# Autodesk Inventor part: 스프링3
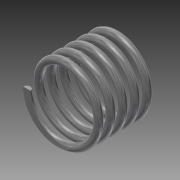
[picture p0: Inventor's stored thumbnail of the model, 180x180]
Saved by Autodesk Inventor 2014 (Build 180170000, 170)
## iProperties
Created: 2016-10
Part Number: 스프링3
Material: 강철, 탄소
Document SubType Name: Modeling
Designer: 703-16
Density: 7.87 g/cm^3
Appearance: 반연마
Mass: 6.81239 g
Surface Area: 17.6676 cm^2
Volume: 0.865614 cm^3
Author: 703-16
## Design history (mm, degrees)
sketch "스케치1"
  geometry: L1 (0, 0)-(-9, 0); L2 (-9, 0)-(-9, 16.67); L3 (-9, 16.67)-(0, 16.67); L4 (0, 16.67)-(0, 0); C1 r 1 at (-9, 0)
  constraints: 8 end point, 2 parallel, 1 centre point, 1 coincident, 1 horizontal, 1 perpendicular
  dimensions: "d0" = 16.66987 distance of L3.end L1.start (derived); "d1" = 2 diameter of C1; "d2" = 18 diameter of L2 L4
feature "코일1" sketch "스케치1" pitch "d3" = 10; turns "d5" = 5; dims "d4" = 16.66987 (= d0), "d6" = 0, angle "d7" = 90 deg, angle "d8" = 90 deg, "d9" = 0, "d10" = 0
node "작업 평면1"
sketch "스케치2"
  geometry: L1 (0, 0)-(-2, 0) reference; 1 further point
  constraints: 1 horizontal alignment
extrude "돌출1" cut sketch "스케치2" distance "d11" = 10; taper "d12" = 0 deg
sketch "스케치3"
  geometry: L1 (8, 0)-(10, 0) reference; 1 further point
  constraints: 1 horizontal alignment
extrude "돌출2" cut sketch "스케치3" distance "d13" = 10; taper "d14" = 0 deg
node "솔리드1"
node "절단 모서리 투영1"
node "절단 모서리 투영2"
